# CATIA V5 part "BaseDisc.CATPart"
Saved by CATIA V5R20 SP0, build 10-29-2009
Part number: BaseDisc
Bounding box of the stored display mesh (mm): x -50 to 50, y -50 to 50, z 0 to 20
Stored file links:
  C:\Users\Robin\Desktop\Delar\BaseDisc.CATPart
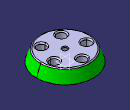
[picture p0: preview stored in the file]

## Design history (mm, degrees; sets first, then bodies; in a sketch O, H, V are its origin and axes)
Body1 (main body)
  Sketch1 on xy-plane, origin (0, 0, 0), H (1, 0, 0), V (0, 1, 0)
    circle A1 centre (0, 0) radius 50
    point P1 (0, 0)
    radius A1 = 50
    coincidence: O P1
  Pad1: profile Sketch1, direction (0, 0, 1), length 20
  Sketch2 on end face of Pad1, origin (0, 0, 20), H (1, 0, 0), V (0, 1, 0)
    point P1 (0, 30)
    distance O P1 = 30
    coincidence: P1 V
  Hole1: placed by Sketch2, at (0, 30, 20) direction (0, 0, -1), diameter 15, through (limit type 3)
  CircPattern1: of Hole1, instances 5, angular step 72 {= 360.0*1 deg/CircPattern1.AngularNumber}, axis from face of Pad1 from Sketch1.A1
  Draft1: PullDir start face of Pad1, Angle 20, SupportToDraft face of Pad1 from Sketch1.A1, Neutral start face of Pad1
  Shell1: IntOffset 2, Face start face of Pad1, ExtOffset 0
  Fillet1: radius 2, on end face of Pad1
  Sketch3 on end face of Pad1, origin (0, 0, 20), H (1, 0, 0), V (0, 1, 0)
    point P1 (0, 0)
    coincidence: P1 O
  Hole2: placed by Sketch3, at (0, 0, 20) direction (0, 0, -1), diameter 10, through (limit type 3)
